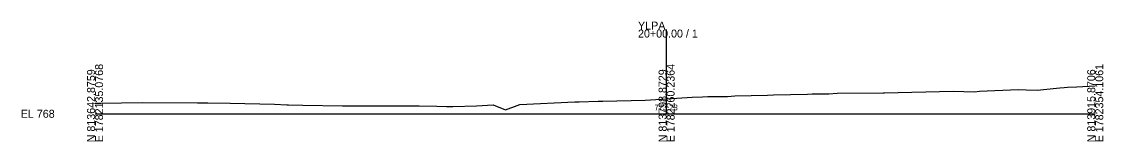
# Model space of a CAD drawing. Extents: x -76 to 1303, y -10 to 9544.
# Drawn here: x 924.3 to 1302.8, y -9.7 to 32.3 of the extents above; entities that cross this region are included whole.
import ezdxf

# ---------------------------------------------------------------- set-up
doc = ezdxf.new("R2010")
doc.units = 0
for name, color, linetype in [('Exist Cross Section Cell', 7, 'Continuous'), ('Exist XS Center Line Elevation Label', 7, 'Continuous'), ('Exist XS Ground Line', 7, 'Continuous')]:
    doc.layers.add(name, color=color, linetype=linetype)

msp = doc.modelspace()

# ---------------------------------------------------------------- linework, layer by layer
at = {"layer": 'Exist Cross Section Cell'}
for p, q in [((1150, 0), (1150, 29.53)), ((950, 0), (1150, 0)), ((1150, 0), (1300, 0))]:
    msp.add_line(p, q, dxfattribs=at)
at = {"layer": 'Exist XS Ground Line'}
for p, q in [((1226.3, 7.33), (1250.25, 7.92)), ((1250.25, 7.92), (1257.79, 7.74)), ((1257.79, 7.74), (1259.53, 7.96)), ((1259.53, 7.96), (1273.01, 8.48)), ((1273.01, 8.48), (1275.78, 8.35)), ((1275.78, 8.35), (1279.81, 8.32)), ((1279.81, 8.32), (1281.85, 8.56)), ((1281.85, 8.56), (1287.63, 9.12)), ((1287.63, 9.12), (1289.08, 9.18)), ((1289.08, 9.18), (1290.25, 9.28)), ((1290.25, 9.28), (1293.5, 9.44)), ((1293.5, 9.44), (1300, 9.84)), ((951.98, 3.78), (966.52, 3.93)), ((966.52, 3.93), (985.83, 3.87)), ((985.83, 3.87), (987.16, 3.88)), ((987.16, 3.88), (989.01, 3.88)), ((989.01, 3.88), (989.46, 3.87)), ((989.46, 3.87), (997.33, 3.71)), ((1098.67, 3.31), (1117.84, 4.19)), ((1117.84, 4.19), (1119.39, 4.23)), ((1119.39, 4.23), (1126.1, 4.39)), ((1126.1, 4.39), (1127.69, 4.47)), ((1127.69, 4.47), (1142.47, 4.73)), ((1142.47, 4.73), (1150, 5.23)), ((1150, 5.23), (1158.92, 5.82)), ((1158.92, 5.82), (1162.59, 5.98)), ((1162.59, 5.98), (1164.4, 6.02)), ((1164.4, 6.02), (1171.29, 6.01)), ((1171.29, 6.01), (1173.91, 6.24)), ((1173.91, 6.24), (1185.29, 6.53)), ((1185.29, 6.53), (1187.36, 6.59)), ((1187.36, 6.59), (1199.36, 6.88)), ((1199.36, 6.88), (1200.91, 6.95)), ((1200.91, 6.95), (1205.51, 7.04)), ((1205.51, 7.04), (1206.81, 7.04)), ((1206.81, 7.04), (1209.7, 7.22)), ((1209.7, 7.22), (1225.82, 7.32)), ((1225.82, 7.32), (1226.3, 7.33)), ((950, 3.73), (951.98, 3.78)), ((997.33, 3.71), (1012.81, 3.34)), ((1012.81, 3.34), (1017.09, 3.17)), ((1017.09, 3.17), (1017.67, 3.19)), ((1017.67, 3.19), (1022.76, 3.07)), ((1022.76, 3.07), (1036.58, 2.81)), ((1036.58, 2.81), (1044.43, 2.77)), ((1044.43, 2.77), (1046.61, 2.76)), ((1046.61, 2.76), (1052.72, 2.81)), ((1052.72, 2.81), (1053.78, 2.82)), ((1053.78, 2.82), (1054.12, 2.82)), ((1054.12, 2.82), (1057.91, 2.82)), ((1057.91, 2.82), (1062.42, 2.81)), ((1062.42, 2.81), (1063.45, 2.82)), ((1063.45, 2.82), (1069.56, 2.71)), ((1069.56, 2.71), (1072.95, 2.54)), ((1072.95, 2.54), (1075.23, 2.52)), ((1075.23, 2.52), (1083.52, 2.84)), ((1083.52, 2.84), (1089.3, 3.09)), ((1089.3, 3.09), (1093.61, 1.42)), ((1093.61, 1.42), (1097.73, 2.96)), ((1097.73, 2.96), (1098.67, 3.31))]:
    msp.add_line(p, q, dxfattribs=at)

# ---------------------------------------------------------------- texts
at = {"layer": 'Exist Cross Section Cell'}
for s, p in [('YLPA', (1140, 29.53)), ('20+00.00 / 1', (1140, 26.73)), ('EL 768', (924, -1.4))]:
    msp.add_text(s, height=2.8, dxfattribs=at).set_placement(p)
for s, p in [('N 813642.8759', (950, -10)), ('E 1782135.0768', (952.8, -10)), ('N 813798.8729', (1150, -10)), ('E 1782260.2364', (1152.8, -10)), ('N 813915.8706', (1300, -10)), ('E 1782354.1061', (1302.8, -10))]:
    msp.add_text(s, height=2.8, rotation=90, dxfattribs=at).set_placement(p)
at = {"layer": 'Exist XS Center Line Elevation Label'}
msp.add_text('773.23', height=2, dxfattribs=at).set_placement((1145.75, 1.23))

doc.saveas('drawing.dxf')
